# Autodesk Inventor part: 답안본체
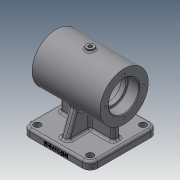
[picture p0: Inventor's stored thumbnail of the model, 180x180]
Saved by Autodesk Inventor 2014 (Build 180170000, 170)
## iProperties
Created: 2019-06
Part Number: 답안본체
Material: 일반
Document SubType Name: Modeling
Designer: net
Density: 1 g/cm^3
Appearance: 기본값
Author: net
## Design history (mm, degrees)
sketch "스케치1"
  geometry: C1 r 32 at (0, 0); 1 further point
  constraints: 1 centre point, 1 coincident
  dimensions: "d0" = 64 diameter of C1
extrude "돌출1" new body sketch "스케치1" stored distance "d1" = 90; taper "d2" = 0 deg
sketch "스케치2"
  geometry: L1 (-32, -45)-(32, -45) reference; L2 (32, 45)-(-32, 45) reference; L3 (0, 45)-(0, -45); L4 (0, 45)-(20, 45); L5 (20, 45)-(20, 30.6); L6 (19.4, 30)-(17, 30); L7 (17, 30)-(17, 24); L8 (17, 24)-(25, 24); L9 (25, 24)-(25, -24); L10 (25, -24)-(17, -24); L11 (17, -24)-(17, -30); L12 (17, -30)-(19.4, -30); L13 (20, -30.6)-(20, -45); L14 (20, -45)-(0, -45); A1 r 0.6 centre (19.4, 30.6) between (19.4, 30) and (20, 30.6); A2 r 0.6 centre (19.4, -30.6) between (20, -30.6) and (19.4, -30); 3 further points
  constraints: 24 end point, 6 parallel, 6 point on line, 4 point on circle, 4 tangent, 3 perpendicular, 2 centre point, 2 midpoint, 1 collinear, 1 equal radius
  dimensions: "d3" = 15 distance of L4.end point (20, 30); "d4" = 15 distance of point (20, -30) L13.end; "d5" = 6 distance of L10.end L11.end; "d6" = 6 distance of L6.end L7.end; "d7" = 40 diameter of L5 L3; "d8" = 40 diameter of L13 L3; "d9" = 34 diameter of L11 L3; "d10" = 34 diameter of L7 L3; "d11" = 50 diameter of L9 L3; "d12" = 0.6 radius of A1
revolve "회전1" sketch "스케치2" stored, may be unused: angle "d13" = 90 deg
chamfer "모따기1" distance "d14" = 1; stored, may be unused: second distance "d15" = 2, angle "d16" = 45 deg
node "작업 평면1"
sketch "스케치3"
  geometry: C1 r 5 at (0, 0); 1 further point
  constraints: 1 centre point, 1 coincident
  dimensions: "d18" = 10 diameter of C1
extrude "돌출2" join sketch "스케치3" stored distance "d19" = 90; taper "d20" = 0 deg
sketch "스케치4"
  geometry: C1 r 5 at (0, 0) reference; 1 further point
  constraints: 1 coincident
hole "구멍1" sketch "스케치4" at (0, 0) diameter "d21" = 4.917; stored, may be unused: countersink angle "d25" = 90 deg, drill point angle "d27" = 118 deg; dims "d22" = 6, "d23" = 4, "d24" = 2, "d26" = 20
fillet "모깎기1" dims "d28" = 2
sketch "스케치5"
  geometry: C1 r 32 at (0, 0) reference; 1 further point
  constraints: 1 horizontal alignment
  dimensions: "d29" = 25 distance of C1.centre point (-25, 0)
hole "구멍2" sketch "스케치5" at (-25, 0) diameter "d30" = 3.242; stored, may be unused: countersink angle "d34" = 90 deg, drill point angle "d36" = 118 deg; dims "d31" = 7, "d32" = 4, "d33" = 2, "d35" = 9
node "작업 평면2"
sketch "스케치6"
  geometry: L1 (45, 45)-(-45, 45); L2 (-45, 45)-(-45, -45); L3 (-45, -45)-(45, -45); L4 (45, -45)-(45, 45); L5 (45, 45)-(-45, -45); L6 (-45, 45)-(45, -45); 1 further point
  constraints: 12 end point, 2 midpoint, 2 parallel, 1 horizontal, 1 perpendicular
  dimensions: "d41" = 90 distance of L3.end L2.end; "d42" = 90 distance of L3.end L1.start
extrude "돌출3" join sketch "스케치6" distance "d43" = 10; taper "d44" = 0 deg
fillet "모깎기2" dims "d45" = 10
fillet "모깎기3" dims "d46" = 3
sketch "스케치7"
  geometry: C1 r 4.5 at (-35, 35); C2 r 4.5 at (-35, -35); C3 r 4.5 at (35, 35); C4 r 4.5 at (35, -35); A1 r 7 centre (35, -35) between (35, -42) and (42, -35) reference; A2 r 7 centre (35, 35) between (42, 35) and (35, 42) reference; A3 r 7 centre (-35, 35) between (-35, 42) and (-42, 35) reference; A4 r 7 centre (-35, -35) between (-42, -35) and (-35, -42) reference; 1 further point
  constraints: 4 centre point, 4 coincident
  dimensions: "d47" = 9 diameter of C1; "d48" = 9 diameter of C2; "d49" = 9 diameter of C3; "d50" = 9 diameter of C4
extrude "돌출4" cut sketch "스케치7" distance "d51" = 10; taper "d52" = 0 deg
sketch "스케치8"
  geometry: L1 (-5, 35)-(5, 35); L2 (5, 35)-(5, -35); L3 (5, -35)-(-5, -35); L4 (-5, -35)-(-5, 35); L5 (-35, -45)-(35, -45) reference; 2 further points
  constraints: 8 end point, 2 parallel, 1 horizontal, 1 midpoint, 1 perpendicular, 1 vertical alignment
  dimensions: "d53" = 10 distance of L2.end L3.end; "d54" = 10 distance between parallel lines of L5 L3; "d55" = 70 distance between parallel lines of L1 L3
extrude "돌출5" join sketch "스케치8" stored distance "d56" = 10; taper "d57" = 0 deg
sketch "스케치9"
  geometry: L1 (-39.5, -55)-(-30.5, -55) reference; L2 (-35, -55)-(35, -55) reference; L3 (-35, -55)-(-23.058, -22.189); L4 (-45, -65)-(-45, -58) reference; 2 further points
  constraints: 2 end point, 1 midpoint, 2 other
  dimensions: "d58" = 10 distance from line of L4 L3.start; "d59" = 110 deg angle of L1 L3
feature "리브1" sketch "스케치9" dims "d60" = 10, "d61" = 10, "d62" = 0, "d63" = 0, "d64" = 1, "d65" = 1
fillet "모깎기4" dims "d66" = 3
fillet "모깎기5" dims "d67" = 3
fillet "모깎기6" dims "d68" = 3
sketch "스케치10"
  geometry: L1 (-35, 45)-(35, 45) reference; L2 (-40, -22.053)-(-40, 22.053); L3 (-37, 25.053)-(-35.053, 25.053); L4 (-25.053, 35.053)-(-25.053, 37); L5 (-22.053, 40)-(22.053, 40); L6 (25.053, 37)-(25.053, 35.053); L7 (35.053, 25.053)-(37, 25.053); L8 (40, 22.053)-(40, -22.053); L9 (37, -25.053)-(35.053, -25.053); L10 (25.053, -35.053)-(25.053, -37); L11 (22.053, -40)-(-22.053, -40); L12 (-25.053, -37)-(-25.053, -35.053); L13 (-35.053, -25.053)-(-37, -25.053); A1 r 10 centre (-35, -35) between (-45, -35) and (-35, -45) reference; A2 r 10 centre (35, -35) between (35, -45) and (45, -35) reference; A3 r 10 centre (35, 35) between (45, 35) and (35, 45) reference; A4 r 10 centre (-35, 35) between (-35, 45) and (-45, 35) reference; A5 r 10 centre (-35, 35) between (-36.026, 25.053) and (-25.053, 36.026); A6 r 10 centre (35, 35) between (25.053, 36.026) and (36.026, 25.053); A7 r 10 centre (-35, -35) between (-25.053, -36.026) and (-36.026, -25.053); A8 r 10 centre (35, -35) between (36.026, -25.053) and (25.053, -36.026); A9 r 10 centre (-35.053, 35.053) between (-35.053, 25.053) and (-25.053, 35.053); A10 r 10 centre (35.053, 35.053) between (25.053, 35.053) and (35.053, 25.053); A11 r 10 centre (35.053, -35.053) between (35.053, -25.053) and (25.053, -35.053); A12 r 10 centre (-35.053, -35.053) between (-25.053, -35.053) and (-35.053, -25.053); A13 r 3 centre (-37, 22.053) between (-37, 25.053) and (-40, 22.053); A14 r 3 centre (-22.053, 37) between (-22.053, 40) and (-25.053, 37); A15 r 3 centre (22.053, 37) between (25.053, 37) and (22.053, 40); A16 r 3 centre (37, 22.053) between (40, 22.053) and (37, 25.053); A17 r 3 centre (37, -22.053) between (37, -25.053) and (40, -22.053); A18 r 3 centre (22.053, -37) between (22.053, -40) and (25.053, -37); A19 r 3 centre (-37, -22.053) between (-40, -22.053) and (-37, -25.053); A20 r 3 centre (-22.053, -37) between (-25.053, -37) and (-22.053, -40); 1 further point
  constraints: 32 point on circle, 24 end point, 24 tangent, 16 centre point, 10 equal radius, 9 parallel, 8 midpoint, 4 coincident, 2 perpendicular, 1 collinear
  dimensions: "d69" = 80 distance between parallel lines of L11 L5; "d70" = 40 distance from line of L5 point (0, 0); "d71" = 80 distance between parallel lines of L2 L8; "d72" = 40 distance from line of L2 point (0, 0); "d73" = 20 diameter of A5; "d74" = 20 diameter of A6; "d75" = 20 diameter of A7; "d76" = 20 diameter of A8; "d77" = 10 radius of A9; "d78" = 3 radius of A13
extrude "돌출6" cut sketch "스케치10" distance "d79" = 5; taper "d80" = 0 deg
sketch "스케치11"
  geometry: L1 (0, 0)-(70, 0) reference; L2 (-10, 7)-(-10, 0) reference; 2 further points
  constraints: 1 other
  dimensions: "d81" = 4 distance from line of L1 point (35, 4); "d82" = 45 distance from line of L2 point (35, 4)
feature "엠보싱1" sketch "스케치11" dims "d3" = 15, "d4" = 15, "d5" = 6, "d6" = 6, "d7" = 40, "d8" = 40, "d9" = 34, "d10" = 34, "d11" = 50, "d12" = 0.6, "d83" = 0.5, "d84" = 0
node "솔리드1"
pattern_circular "원형 패턴1" dims angle "d38" = 360 deg
mirror "대칭1"
mirror "대칭2"
node "투영된 루프1"
other parameters: "d17" = 35, "d40" = -65
